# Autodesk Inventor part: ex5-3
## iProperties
Author: Administrator
Created: 2001-09
Part Number: ex5-3
Document SubType Name: Modeling
Designer: Administrator
Control State: 0
Master: False
Checked Out: False
PropertySet Name: Design Tracking Control
Length Units: 11272
Angle Units: 11279
Time Units: 11290
Mass Units: 11286
Shininess: 3
Angle Display Precision: 2
Document Length Units: 11272
Document Angle Units: 11286
Document Time Units: 11279
Document Mass Units: 11290
Document Length Units Precision: 3
Document Angle Units Precision: 2
Compacted: False
PropertySet Name: _Private Model Information
Density: 0.0
Volumn: 0.0
Area: 0.0
PropertySet Name: Model Information
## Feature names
1. Revolution1
2. Hole1
3. Shell1
